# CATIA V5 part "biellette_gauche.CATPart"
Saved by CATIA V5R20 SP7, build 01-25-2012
Part number: biellette_gauche
Bounding box of the stored display mesh (mm): x -229.954 to -38.796, y 670.046 to 802.574, z -20 to 0
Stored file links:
  U:\IAO\thinkmotion catia2\biellette_gauche.CATPart
  U:\IAO\thinkmotion catia2\Ass_862_adubourgno.CATProduct
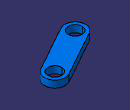
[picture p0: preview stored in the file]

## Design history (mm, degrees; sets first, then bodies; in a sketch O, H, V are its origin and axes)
Set1
  Plane1: linked copy from another document
  Point1 "B2": linked copy from another document
  Point2 "E": linked copy from another document
Body1 (main body)
  Sketch1 on Plane1, origin (0, 0, 0), H (1, 0, 0), V (0, 1, 0)
    arc A1 centre (-68.75, 772.62) radius 30 from (-54.2261, 746.3701) to (-83.2739, 798.8699) ccw
    point P1 (-68.75, 772.62)
    reference projected point E1 (-68.75, 772.62) from Point1
    axis line L1 (-200, 700) -> (-68.75, 772.62)
    point P2 (-200, 700)
    point P3 (-68.75, 772.62)
    reference projected point E2 (-68.75, 772.62) from Point1
    reference projected point E3 (-200, 700) from Point2
    arc A2 centre (-200, 700) radius 30 from (-214.5239, 726.2499) to (-185.4761, 673.7501) ccw
    point P4 (-200, 700)
    reference projected point E4 (-200, 700) from Point2
    line L2 (-214.5239, 726.2499) -> (-83.2739, 798.8699)
    line L3 (-185.4761, 673.7501) -> (-54.2261, 746.3701)
    point P7 (-54.2261, 746.3701)
    point P8 (-185.4761, 673.7501)
    reference projected point E5 (-68.75, 772.62) from Point1
    reference projected point E6 (-200, 700) from Point2
    circle A3 centre (-68.75, 772.62) radius 20
    point P9 (-68.75, 772.62)
    reference projected point E7 (-68.75, 772.62) from Point1
    circle A4 centre (-200, 700) radius 20
    point P10 (-200, 700)
    reference projected point E8 (-200, 700) from Point2
    radius A1 = 30
    distance E1 P1 = 0
    distance E2 P3 = 0
    distance E3 P2 = 0
    radius A2 = 30
    distance E4 P4 = 0
    distance L2 L1 = 30
    distance L3 L1 = 30
    distance E5 P7 = 30
    distance E6 P8 = 30
    radius A3 = 20
    distance E7 P9 = 0
    radius A4 = 20
    distance E8 P10 = 0
  Pad1: profile Sketch1, direction (0, 0, -1), length 20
